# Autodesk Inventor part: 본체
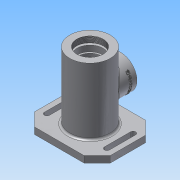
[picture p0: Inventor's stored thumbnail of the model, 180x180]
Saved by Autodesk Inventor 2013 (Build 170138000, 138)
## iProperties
Created: 2017-10
Part Number: 본체
Material: 알루미늄 6061
Document SubType Name: Modeling
Designer: Administrator
Density: 2.71 g/cm^3
Mass: 740.875 g
Surface Area: 653.463 cm^2
Volume: 273.385 cm^3
Author: Administrator
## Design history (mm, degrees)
sketch "스케치1"
  geometry: L1 (-38, -47)-(38, -47); L2 (58, -27)-(58, 27); L3 (38, 47)-(-38, 47); L4 (-58, 27)-(-58, -27); L5 (-58, -47)-(58, 47); L6 (58, -47)-(-58, 47); L7 (-50, 20)-(-50, -20); L8 (-42, 20)-(-42, -20); L9 (42, 20)-(42, -20); L10 (50, 20)-(50, -20); L11 (-38, 47)-(-58, 27); L12 (-58, -27)-(-38, -47); L13 (38, -47)-(58, -27); L14 (58, 27)-(38, 47); A1 r 4 centre (46, 20) between (50, 20) and (42, 20); A2 r 4 centre (46, -20) between (42, -20) and (50, -20); A3 r 4 centre (-46, -20) between (-50, -20) and (-42, -20); A4 r 4 centre (-46, 20) between (-42, 20) and (-50, 20); 3 further points
  constraints: 28 end point, 8 point on circle, 8 point on line, 7 tangent, 4 centre point, 3 equal radius, 3 midpoint, 3 parallel, 2 horizontal alignment, 2 vertical alignment, 1 coincident, 1 horizontal, 1 perpendicular
  dimensions: "d0" = 116 distance of L6.end L5.end; "d1" = 94 distance of L5.end L6.start; "d2" = 20 vertical distance of A2.centre point (0, 0); "d3" = 40 distance of A1.centre A2.centre; "d4" = 46 horizontal distance of A3.centre point (0, 0); "d5" = 92 distance of A2.centre A3.centre; "d6" = 8 diameter of A1; "d7" = 20 distance of L3.end L6.end; "d8" = 20 distance of L4.start L6.end (= d7); "d9" = 20 distance of L4.end L5.start (= d7); "d10" = 20 distance of L1.start L5.start (= d9); "d11" = 20 distance of L1.end L6.start (= d7); "d12" = 20 distance of L2.start L6.start (= d11); "d13" = 20 distance of L2.end L5.end (= d7); "d14" = 20 distance of L3.start L5.end (= d13)
extrude "돌출1" new body sketch "스케치1" distance "d15" = 10; taper "d16" = 0 deg
sketch "스케치2"
  geometry: C1 r 31 at (0, 0); 1 further point
  constraints: 1 centre point, 1 coincident
  dimensions: "d17" = 62 diameter of C1
extrude "돌출2" join sketch "스케치2" distance "d18" = 102; taper "d19" = 0 deg
sketch "스케치3"
  geometry: C1 r 35 at (0, 0); 1 further point
  constraints: 1 centre point, 1 coincident
  dimensions: "d20" = 70 diameter of C1
extrude "돌출3" join sketch "스케치3" distance "d21" = 3; taper "d22" = 0 deg
sketch "스케치4"
  geometry: L1 (-35, -3)-(35, -3) reference; L2 (-31, 10)-(-31, 112) reference; L3 (31, 112)-(-31, 112) reference; L4 (31, 10)-(31, 112) reference; L5 (0, 112)-(0, -3); L6 (22, -3)-(16, 11); L7 (16, 11)-(12.5, 11); L8 (12.5, 11)-(12.5, 18.3); L9 (12.5, 18.3)-(10, 18.3); L10 (10, 18.3)-(10, 21); L11 (10, 21)-(16.5, 21); L12 (16.5, 21)-(16.5, 26); L13 (16.5, 26)-(17.5, 26); L14 (17.5, 26)-(17.5, 37); L15 (17.5, 37)-(26, 37); L16 (26, 37)-(26, 75); L17 (26, 75)-(17.5, 75); L18 (17.5, 75)-(17.5, 84.25); L19 (17.5, 84.25)-(18.5, 84.25); L20 (18.5, 84.25)-(18.5, 86); L21 (18.5, 86)-(17.5, 86); L22 (17.5, 86)-(17.5, 91); L23 (17.5, 91)-(20, 91); L24 (20, 91)-(20, 100); L25 (20, 100)-(24, 100); L26 (24, 100)-(24, 103); L27 (24, 103)-(0, 103); L28 (22, -3)-(0, -3); 1 further point
  constraints: 48 end point, 21 perpendicular, 2 midpoint, 2 point on line, 1 parallel
  dimensions: "d26" = 14 distance between parallel lines of L7 L28; "d27" = 7.3 distance between parallel lines of L9 L7; "d28" = 2.7 distance between parallel lines of L11 L9; "d32" = 22 distance of L5.end L6.start; "d33" = 32 diameter of L6.end L5; "d34" = 25 diameter of L8 L5; "d35" = 20 diameter of L10 L5; "d36" = 33 diameter of L12 L5; "d37" = 5 distance of L11.end L12.end; "d38" = 11 distance of L13.end L14.end; "d39" = 35 diameter of L14 L5; "d40" = 52 diameter of L16 L5; "d41" = 38 distance of L15.end L16.end; "d43" = 35 diameter of L18 L5; "d44" = 11 distance between parallel lines of L21 L17; "d45" = 1.75 distance of L19.end L20.end; "d46" = 37 diameter of L20 L5; "d47" = 35 diameter of L22 L5; "d48" = 12 distance between parallel lines of L25 L3; "d49" = 3 distance between parallel lines of L25 L27; "d50" = 48 diameter of L26 L5; "d51" = 40 diameter of L24 L5; "d52" = 21 distance between parallel lines of L23 L3
revolve "회전1" sketch "스케치4" stored, may be unused: angle "d53" = 90 deg
sketch "스케치5"
  geometry: C1 r 31 at (0, 0) reference
hole "구멍1" sketch "스케치5" at (0, 0) diameter "d54" = 40.376; stored, may be unused: countersink angle "d58" = 90 deg, drill point angle "d60" = 0 deg; dims "d55" = 6, "d56" = 48, "d57" = 3, "d59" = 9
sketch "스케치6"
  geometry: L1 (76, 0)-(0, 0) reference; L2 (7, -112)-(69, -112) reference; C1 r 25 at (38, -56); 2 further points
  constraints: 1 centre point, 1 midpoint, 1 vertical alignment
  dimensions: "d61" = 50 diameter of C1; "d62" = 56 distance from line of C1.centre L2
extrude "돌출4" join sketch "스케치6" stored distance "d63" = 3; taper "d64" = 0 deg
sketch "스케치7"
  geometry: C1 r 25 at (0, 0) reference; 1 further point
hole "구멍2" sketch "스케치7" at (0, 0) diameter "d65" = 32; stored, may be unused: countersink angle "d69" = 90 deg, drill point angle "d71" = 0 deg; dims "d66" = 6, "d67" = 48, "d68" = 3, "d70" = 9
sketch "스케치8"
  geometry: C1 r 16 at (0, 0) reference; C2 r 25 at (0, 0) reference; A1 r 20.5 centre (0, 0) between (-20.5, 0) and (20.5, 0); 1 further point
  constraints: 2 horizontal alignment, 2 point on circle, 1 centre point, 1 coincident
  dimensions: "d72" = 41 diameter of A1
hole "구멍3" sketch "스케치8" at (-20.5, 0), (20.5, 0) diameter "d73" = 2.459; stored, may be unused: countersink angle "d77" = 90 deg, drill point angle "d79" = 118 deg; dims "d74" = 6, "d75" = 48, "d76" = 3, "d78" = 8
node "작업 평면1"
sketch "스케치9"
  geometry: L1 (31, 112)-(-31, 112) reference; L2 (47, 81)-(47, 31) reference; 2 further points
  constraints: 1 other
  dimensions: "d81" = 56 distance from line of point (37, 56) L1; "d82" = 10 distance from line of point (37, 56) L2
feature "엠보싱1" sketch "스케치9" dims "d0" = 116, "d1" = 94, "d7" = 20, "d8" = 20 (= d7), "d9" = 20 (= d7), "d10" = 20 (= d9), "d11" = 20 (= d7), "d12" = 20 (= d11), "d13" = 20 (= d7), "d14" = 20 (= d13), "d83" = 0.5, "d84" = 0
chamfer "모따기1" distance "d85" = 1; stored, may be unused: second distance "d86" = 2, angle "d87" = 45 deg
chamfer "모따기2" distance "d88" = 0.7; stored, may be unused: second distance "d89" = 2, angle "d90" = 30 deg
fillet "모깎기1" dims "d91" = 0.3, "d92" = 3
node "솔리드1"
other parameters: "d80" = 25.5
